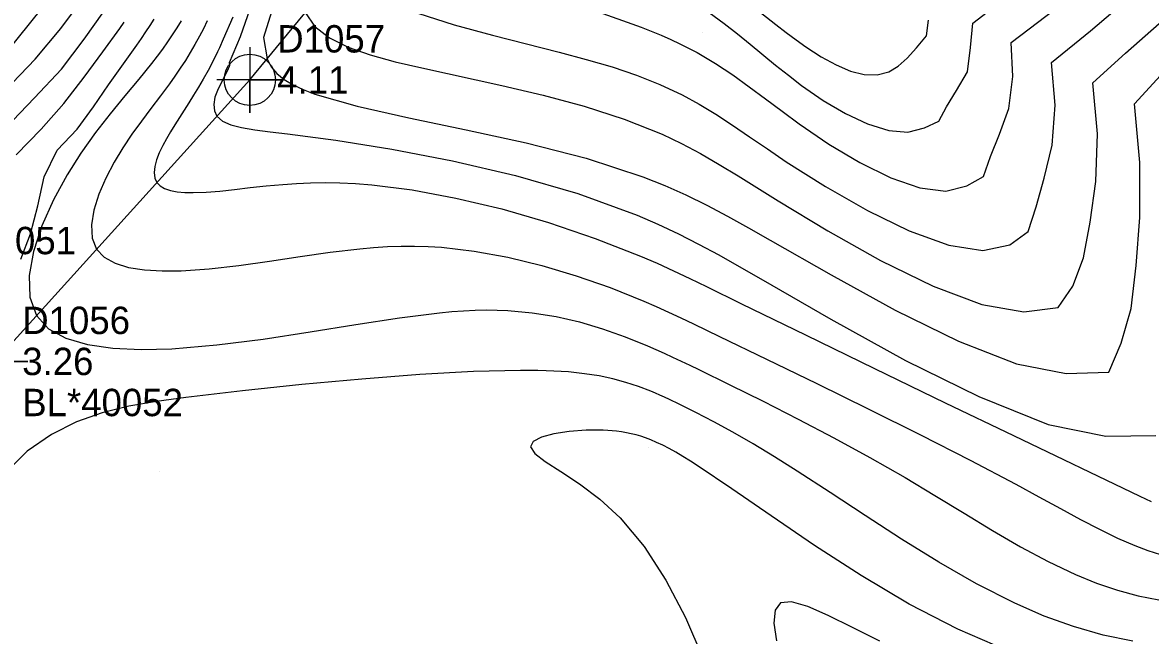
# Model space of a CAD drawing. Extents: x 2356077 to 2359823, y 225951 to 227822.
# Drawn here: x 2357294.1 to 2357397.1, y 226556.7 to 226612.7 of the extents above; entities that cross this region are included whole.
import ezdxf

# ---------------------------------------------------------------- set-up
doc = ezdxf.new("R2010")
doc.units = 0
for name, color, linetype in [('DTM Contours Major', 7, 'Continuous'), ('DTM Contours Minor', 7, 'Continuous'), ('Exist DTM Breakline', 7, 'Continuous'), ('Exist DTM Breakline Cogo Comment', 7, 'Continuous'), ('Exist DTM Breakline Cogo Elevation', 7, 'Continuous'), ('Exist DTM Breakline Cogo Number', 7, 'Continuous'), ('Exist DTM Breakline Cogo Point CELL', 7, 'Continuous'), ('PH Exist DTM Point', 7, 'Continuous')]:
    doc.layers.add(name, color=color, linetype=linetype)

msp = doc.modelspace()

# ---------------------------------------------------------------- linework, layer by layer
at = {"layer": 'DTM Contours Major'}
for points in [[(2357356.82, 226613.62), (2357358.2, 226612.62), (2357359.41, 226611.68), (2357360.59, 226610.73), (2357362.9, 226608.82), (2357364.07, 226607.89), (2357365.27, 226606.97), (2357367.26, 226605.6), (2357369.29, 226604.4), (2357371.31, 226603.45), (2357373.23, 226602.86), (2357374.99, 226602.71), (2357376.51, 226603.09), (2357377.81, 226603.7), (2357378.51, 226605.02), (2357379.44, 226606.5), (2357380.44, 226608.22), (2357380.71, 226610.43), (2357380.91, 226612.66), (2357389.57, 226619.31)], [(2357314.87, 226613.92), (2357314, 226611.39), (2357313, 226609.04), (2357313.03, 226608.88), (2357313.01, 226608.77), (2357312.98, 226608.67), (2357312.9, 226608.48), (2357312.86, 226608.39), (2357311.98, 226606.65), (2357311.68, 226605.88), (2357311.6, 226605.21), (2357311.65, 226604.63), (2357311.88, 226604.16), (2357312.38, 226603.71), (2357313.14, 226603.37), (2357314.13, 226603.12), (2357315.34, 226602.91), (2357316.74, 226602.73), (2357318.33, 226602.54), (2357322.75, 226601.95), (2357327.85, 226601.14), (2357333.39, 226600.07), (2357339.14, 226598.73), (2357344.84, 226597.09), (2357350.26, 226595.11), (2357352.16, 226594.28), (2357354.02, 226593.4), (2357355.86, 226592.47), (2357357.71, 226591.48), (2357359.59, 226590.43), (2357361.55, 226589.31), (2357367.96, 226585.63), (2357374.78, 226581.85), (2357381.47, 226578.56), (2357387.8, 226576), (2357393.08, 226574.93), (2357397.63, 226575)], [(2357293.55, 226600.62), (2357295.81, 226602.98), (2357297.9, 226605.3), (2357299.74, 226607.73), (2357301.46, 226610.04), (2357303, 226612.16), (2357303.4, 226612.73)], [(2357382.93, 226555.85), (2357379.54, 226557.3), (2357375.11, 226559.59), (2357370.72, 226562.2), (2357366.47, 226564.95), (2357362.5, 226567.65), (2357358.91, 226570.13), (2357355.84, 226572.19), (2357355.12, 226572.66), (2357354.44, 226573.08), (2357353.79, 226573.46), (2357353.17, 226573.8), (2357352.59, 226574.11), (2357352.02, 226574.37), (2357351.52, 226574.59), (2357351.03, 226574.78), (2357350.59, 226574.92), (2357350.16, 226575.05), (2357349.72, 226575.16), (2357349.28, 226575.25), (2357348.84, 226575.32), (2357348.38, 226575.38), (2357347.98, 226575.42), (2357347.57, 226575.45), (2357347.15, 226575.47), (2357345.6, 226575.47), (2357344.06, 226575.36), (2357342.65, 226575.15), (2357341.51, 226574.85), (2357340.75, 226574.45), (2357340.51, 226573.97), (2357340.9, 226573.36), (2357341.87, 226572.62), (2357343.28, 226571.7), (2357344.99, 226570.57), (2357346.84, 226569.17), (2357348.71, 226567.47), (2357350.89, 226564.86), (2357352.88, 226561.78), (2357354.67, 226558.36), (2357356.27, 226554.68)]]:
    msp.add_lwpolyline(points, dxfattribs=at)
at = {"layer": 'DTM Contours Minor'}
for points in [[(2357289.74, 226603.6), (2357295.26, 226609.37), (2357297.63, 226612.17), (2357299.79, 226615.07)], [(2357317.01, 226614.18), (2357316.12, 226611.34), (2357316.46, 226609.38), (2357316.84, 226608.66), (2357317.36, 226608.04), (2357318.03, 226607.49), (2357318.83, 226607.01), (2357319.76, 226606.58), (2357320.81, 226606.18), (2357324.69, 226605.06), (2357329.39, 226604), (2357334.63, 226602.92), (2357340.13, 226601.72), (2357345.61, 226600.32), (2357350.79, 226598.63), (2357352.78, 226597.83), (2357354.71, 226596.96), (2357356.61, 226596.03), (2357358.51, 226595.03), (2357360.43, 226593.97), (2357362.42, 226592.84), (2357367.98, 226589.66), (2357373.83, 226586.45), (2357379.6, 226583.6), (2357384.92, 226581.54), (2357389.43, 226580.66), (2357393.34, 226580.77), (2357394.46, 226583.43), (2357395.39, 226586.58), (2357395.85, 226590.51), (2357396.16, 226594.89), (2357396.16, 226599.92), (2357395.69, 226605.29), (2357398.06, 226607.88)], [(2357330.23, 226613.57), (2357333.55, 226612.5), (2357337.05, 226611.55), (2357343.13, 226610.01), (2357345.61, 226609.34), (2357347.97, 226608.65), (2357350.21, 226607.89), (2357352.34, 226607.05), (2357354.38, 226606.1), (2357355.93, 226605.25), (2357357.45, 226604.33), (2357358.97, 226603.33), (2357360.53, 226602.27), (2357362.15, 226601.16), (2357363.87, 226600), (2357367.47, 226597.72), (2357371.29, 226595.53), (2357375.11, 226593.67), (2357378.71, 226592.38), (2357381.84, 226591.88), (2357384.29, 226592.42), (2357385.97, 226593.62), (2357386.69, 226595.87), (2357387.44, 226598.5), (2357388.15, 226601.51), (2357388.43, 226605.15), (2357388.09, 226609.06), (2357391.66, 226611.94), (2357395.14, 226614.94)], [(2357360.95, 226614.07), (2357362.93, 226612.53), (2357363.86, 226611.81), (2357364.77, 226611.13), (2357365.66, 226610.49), (2357367.06, 226609.58), (2357368.42, 226608.83), (2357369.74, 226608.28), (2357370.99, 226607.96), (2357372.17, 226607.93), (2357373.26, 226608.22), (2357374.1, 226608.73), (2357374.92, 226609.46), (2357375.77, 226610.4), (2357376.69, 226611.5), (2357376.86, 226612.93)], [(2357289.89, 226600.28), (2357295.21, 226605.84), (2357297.69, 226608.44), (2357299.76, 226611.2), (2357301.55, 226613.72)], [(2357293.96, 226591.1), (2357294.85, 226593.41), (2357295.51, 226595.96), (2357296.11, 226598.63), (2357297.29, 226601.05), (2357299.12, 226602.96), (2357300.59, 226605), (2357301.98, 226607.02), (2357304.56, 226610.64), (2357304.99, 226611.26), (2357305.39, 226611.85), (2357305.78, 226612.44), (2357306.15, 226613.01)], [(2357313.33, 226613.19), (2357312.46, 226611.19), (2357312.1, 226610.4), (2357311.92, 226610.03), (2357311.49, 226609.16), (2357311.06, 226608.33), (2357310.62, 226607.55), (2357310.19, 226606.79), (2357309.75, 226606.07), (2357309.31, 226605.36), (2357308.02, 226603.36), (2357307.63, 226602.72), (2357307.26, 226602.09), (2357306.92, 226601.47), (2357306.61, 226600.8), (2357306.36, 226600.16), (2357306.2, 226599.55), (2357306.14, 226599), (2357306.2, 226598.5), (2357306.38, 226598.09), (2357306.68, 226597.78), (2357307.1, 226597.54), (2357307.63, 226597.37), (2357308.25, 226597.25), (2357308.94, 226597.19), (2357309.71, 226597.18), (2357310.88, 226597.22), (2357312.14, 226597.32), (2357313.49, 226597.47), (2357314.91, 226597.63), (2357316.38, 226597.79), (2357317.91, 226597.93), (2357319.15, 226598.02), (2357320.43, 226598.07), (2357321.75, 226598.1), (2357323.11, 226598.08), (2357324.53, 226598.01), (2357326.01, 226597.9), (2357329.71, 226597.43), (2357333.7, 226596.68), (2357337.89, 226595.68), (2357342.16, 226594.45), (2357346.42, 226593), (2357350.57, 226591.37), (2357352.08, 226590.72), (2357353.57, 226590.04), (2357355.07, 226589.33), (2357356.59, 226588.6), (2357359.78, 226587.03), (2357365.62, 226584.18), (2357371.94, 226581.11), (2357378.4, 226577.99), (2357384.64, 226574.99), (2357396.18, 226569.44), (2357397.2, 226568.96)], [(2357319.93, 226613.61), (2357320.82, 226612.35), (2357322.15, 226611.32), (2357323.86, 226610.47), (2357325.88, 226609.75), (2357328.14, 226609.13), (2357330.58, 226608.56), (2357337.9, 226606.96), (2357341.68, 226606.07), (2357345.43, 226605.06), (2357349.07, 226603.89), (2357352.53, 226602.5), (2357354.31, 226601.66), (2357356.03, 226600.74), (2357357.75, 226599.75), (2357359.48, 226598.7), (2357363.13, 226596.43), (2357367.68, 226593.67), (2357372.49, 226590.97), (2357377.29, 226588.62), (2357381.75, 226586.96), (2357385.58, 226586.28), (2357388.72, 226586.68), (2357390.05, 226588.62), (2357391.01, 226591.22), (2357391.62, 226594.49), (2357392.14, 226598.18), (2357392.3, 226602.53), (2357391.89, 226607.19), (2357394.85, 226609.9), (2357397.95, 226612.62)], [(2357346.26, 226613.84), (2357350.61, 226612.29), (2357351.55, 226611.92), (2357352.46, 226611.54), (2357353.33, 226611.15), (2357354.16, 226610.76), (2357354.96, 226610.37), (2357355.74, 226609.96), (2357357.42, 226608.97), (2357358.99, 226607.93), (2357360.5, 226606.85), (2357361.99, 226605.73), (2357363.49, 226604.6), (2357365.05, 226603.45), (2357367.77, 226601.61), (2357370.61, 226599.92), (2357373.43, 226598.54), (2357376.09, 226597.62), (2357378.45, 226597.32), (2357380.37, 226597.79), (2357381.89, 226598.65), (2357382.52, 226600.46), (2357383.35, 226602.51), (2357384.22, 226604.86), (2357384.57, 226607.79), (2357384.43, 226610.87), (2357388.46, 226613.97)], [(2357308.6, 226612.86), (2357308.2, 226612.21), (2357307.79, 226611.57), (2357307.35, 226610.93), (2357306.89, 226610.28), (2357306.41, 226609.63), (2357305.89, 226608.97), (2357304.73, 226607.54), (2357303.46, 226606.01), (2357302.13, 226604.38), (2357300.79, 226602.65), (2357299.46, 226600.79), (2357298.19, 226598.81), (2357296.94, 226596.51), (2357295.88, 226594.14), (2357295.12, 226591.81), (2357294.73, 226589.6), (2357294.79, 226587.62), (2357295.39, 226585.95), (2357296.49, 226584.75), (2357298.07, 226583.87), (2357300.06, 226583.29), (2357302.38, 226582.96), (2357304.96, 226582.85), (2357307.75, 226582.92), (2357311.86, 226583.26), (2357316.11, 226583.8), (2357320.38, 226584.45), (2357324.56, 226585.13), (2357328.54, 226585.74), (2357332.19, 226586.2), (2357333.32, 226586.31), (2357334.41, 226586.39), (2357335.46, 226586.44), (2357336.48, 226586.46), (2357337.47, 226586.45), (2357338.45, 226586.42), (2357340.68, 226586.21), (2357342.86, 226585.86), (2357344.99, 226585.37), (2357347.08, 226584.75), (2357349.15, 226584.02), (2357351.2, 226583.19), (2357351.96, 226582.86), (2357352.72, 226582.51), (2357353.49, 226582.16), (2357355.07, 226581.41), (2357355.88, 226581.02), (2357358.73, 226579.63), (2357361.78, 226578.12), (2357364.96, 226576.5), (2357368.22, 226574.79), (2357371.5, 226573), (2357374.74, 226571.15), (2357377.46, 226569.52), (2357380.12, 226567.9), (2357382.72, 226566.33), (2357385.28, 226564.84), (2357387.79, 226563.48), (2357390.28, 226562.29), (2357392.2, 226561.51), (2357394.12, 226560.86), (2357396.02, 226560.34), (2357397.92, 226559.98)], [(2357310.99, 226612.85), (2357310.64, 226612.14), (2357310.28, 226611.46), (2357309.87, 226610.7), (2357309.43, 226609.96), (2357308.99, 226609.24), (2357308.52, 226608.53), (2357308.04, 226607.82), (2357307.53, 226607.11), (2357306.71, 226606), (2357305.85, 226604.87), (2357304.98, 226603.7), (2357304.11, 226602.5), (2357303.27, 226601.25), (2357302.49, 226599.95), (2357301.72, 226598.49), (2357301.09, 226597.02), (2357300.64, 226595.58), (2357300.42, 226594.24), (2357300.49, 226593.03), (2357300.89, 226592.02), (2357301.58, 226591.28), (2357302.57, 226590.73), (2357303.8, 226590.35), (2357305.25, 226590.12), (2357306.86, 226590.02), (2357308.6, 226590.04), (2357311.18, 226590.22), (2357313.89, 226590.53), (2357316.67, 226590.92), (2357319.47, 226591.34), (2357322.23, 226591.73), (2357324.92, 226592.04), (2357326.19, 226592.16), (2357327.45, 226592.24), (2357328.69, 226592.28), (2357329.92, 226592.28), (2357331.16, 226592.25), (2357332.4, 226592.18), (2357335.38, 226591.84), (2357338.44, 226591.28), (2357341.55, 226590.52), (2357344.68, 226589.59), (2357347.8, 226588.5), (2357350.86, 226587.27), (2357351.99, 226586.77), (2357353.11, 226586.27), (2357354.25, 226585.74), (2357355.4, 226585.19), (2357357.78, 226584.04), (2357362.06, 226581.97), (2357366.66, 226579.73), (2357371.41, 226577.4), (2357376.13, 226575.05), (2357380.67, 226572.74), (2357384.84, 226570.55), (2357386.95, 226569.4), (2357388.91, 226568.33), (2357390.75, 226567.33), (2357392.48, 226566.43), (2357394.12, 226565.63), (2357395.7, 226564.94), (2357396.89, 226564.49), (2357398.05, 226564.12)], [(2357395.52, 226556.22), (2357392.82, 226556.77), (2357390.12, 226557.54), (2357387.43, 226558.51), (2357384.74, 226559.68), (2357381.26, 226561.44), (2357377.8, 226563.42), (2357374.39, 226565.54), (2357371.08, 226567.69), (2357367.89, 226569.79), (2357364.87, 226571.75), (2357362.8, 226573.04), (2357360.84, 226574.22), (2357358.99, 226575.29), (2357357.25, 226576.25), (2357355.61, 226577.11), (2357354.08, 226577.87), (2357353.2, 226578.29), (2357352.77, 226578.49), (2357352.34, 226578.67), (2357351.92, 226578.86), (2357351.5, 226579.03), (2357350.37, 226579.46), (2357349.22, 226579.84), (2357348.03, 226580.16), (2357346.78, 226580.43), (2357345.44, 226580.64), (2357343.99, 226580.8), (2357343.33, 226580.84), (2357342.65, 226580.88), (2357341.94, 226580.91), (2357341.19, 226580.93), (2357340.41, 226580.94), (2357339.6, 226580.94), (2357335.31, 226580.83), (2357330.4, 226580.56), (2357325.1, 226580.15), (2357319.63, 226579.65), (2357314.2, 226579.07), (2357309.05, 226578.46), (2357306.37, 226578.1), (2357303.82, 226577.66), (2357301.39, 226577.06), (2357299.04, 226576.23), (2357296.76, 226575.09), (2357294.54, 226573.57), (2357290.28, 226569.3)], [(2357372.43, 226556.2), (2357369.93, 226557.46), (2357367.71, 226558.56), (2357365.84, 226559.38), (2357364.36, 226559.8), (2357363.35, 226559.7), (2357362.85, 226559.04), (2357362.74, 226557.86), (2357362.97, 226556.23)]]:
    msp.add_lwpolyline(points, dxfattribs=at)
at = {"layer": 'Exist DTM Breakline'}
for points in [[(2357281.82, 226596.55), (2357301.26, 226620.71), (2357322.99, 226644.43), (2357334.58, 226670.67), (2357330.12, 226701.28)], [(2357291.59, 226581.76), (2357314.88, 226607.47), (2357338.68, 226636.37), (2357349.9, 226670.66), (2357351.86, 226686.88)]]:
    msp.add_lwpolyline(points, dxfattribs=at)
at = {"layer": 'Exist DTM Breakline Cogo Point CELL'}
for points in [[(2357314.88, 226610.47), (2357314.88, 226604.47), (2357314.88, 226607.47), (2357317.88, 226607.47), (2357311.88, 226607.47)], [(2357291.59, 226584.76), (2357291.59, 226578.76), (2357291.59, 226581.76), (2357294.59, 226581.76), (2357288.59, 226581.76)]]:
    msp.add_lwpolyline(points, dxfattribs=at)
msp.add_circle((2357314.88, 226607.47), 2.34, dxfattribs=at)
at = {"layer": 'PH Exist DTM Point'}
for p, q in [((2357356.19, 226611.82), (2357356.19, 226611.82)), ((2357351.3, 226573.91), (2357351.3, 226573.91)), ((2357306.6, 226571.7), (2357306.6, 226571.7))]:
    msp.add_line(p, q, dxfattribs=at)

# ---------------------------------------------------------------- texts
at = {"layer": 'Exist DTM Breakline Cogo Comment'}
for s, p in [('BL*40051', (2357284.32, 226591.55)), ('BL*40052', (2357294.09, 226576.76))]:
    msp.add_text(s, height=2.5, dxfattribs=at).set_placement(p)
at = {"layer": 'Exist DTM Breakline Cogo Elevation'}
for s, p in [('4.11', (2357317.38, 226606.22)), ('3.26', (2357294.09, 226580.51))]:
    msp.add_text(s, height=2.5, dxfattribs=at).set_placement(p)
at = {"layer": 'Exist DTM Breakline Cogo Number'}
for s, p in [('D1057', (2357317.38, 226609.97)), ('D1056', (2357294.09, 226584.26))]:
    msp.add_text(s, height=2.5, dxfattribs=at).set_placement(p)

doc.saveas('drawing.dxf')
